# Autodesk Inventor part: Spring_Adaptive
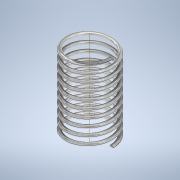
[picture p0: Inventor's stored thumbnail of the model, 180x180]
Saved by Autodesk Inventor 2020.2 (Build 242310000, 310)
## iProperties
Created: 2020-01
Part Number: Spring_Adaptive
Material: Nickel-Copper Alloy 400
Document SubType Name: Modeling
Designer: thira
Density: 8.83 g/cm^3
Appearance: Chrome - Polished
Author: thira
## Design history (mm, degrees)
sketch "Sketch1"
  geometry: C1 r 100 at (0, 0); 1 further point
  constraints: 1 centre point, 1 coincident
  dimensions: "d0" = 200 diameter of C1
extrude "Extrusion1" new body sketch "Sketch1" taper "d2" = 0 deg; distance "Height" = 330
sketch "Sketch2"
  geometry: L1 (100, 330)-(100, 0) reference; L2 (100, 0)-(-100, 0) reference; L3 (-100, 0)-(-100, 330) reference; L4 (-100, 330)-(100, 330) reference; L5 (100, 0)-(-100, 0) reference; C1 r 7.5 at (92.5, 0); 1 further point
  constraints: 1 centre point, 1 point on line, 1 tangent
  dimensions: "d3" = 15 diameter of C1
coil "Coil1" sketch "Sketch2" pitch "d4" = 33 (= 0.1 x Height); turns "d6" = 1; dims "d5" = 330 (= Height), "d7" = 0, angle "d8" = 90 deg, angle "d9" = 90 deg, "d10" = 0, "d11" = 0
body "Solid1"
node "Project Cut Edges1"
